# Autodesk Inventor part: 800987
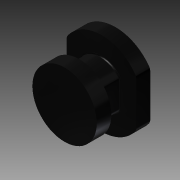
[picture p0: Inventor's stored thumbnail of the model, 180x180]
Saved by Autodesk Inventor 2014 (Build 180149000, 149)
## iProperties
Created: 2007-10
Part Number: 800987
Document SubType Name: Modeling
Designer: TH
Density: 7.85 g/cm^3
Mass: 11.8933 g
Surface Area: 10.7394 cm^2
Volume: 1.51507 cm^3
Material: Steel
Description: CONNECTOR PIN
Appearance: Glossy - Black
Component Category: Fasteners
Author: TH
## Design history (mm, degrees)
sketch "Sketch1"
  geometry: L1 (0, 0)-(0, -10.95); L2 (0, -10.95)-(6.925, -10.95); L3 (6.925, -10.95)-(6.925, -7.8); L4 (6.925, -7.8)-(5, -7.8); L5 (5, -7.8)-(5, -3); L6 (5, -3)-(9, -3); L7 (9, -3)-(9, 0); L8 (9, 0)-(0, 0)
  constraints: 16 end point, 6 parallel, 1 perpendicular, 1 vertical
  dimensions: "d0" = 6.925 distance of L1.end L2.end; "d1" = 5 distance between parallel lines of L1 L5; "d2" = 9 distance between parallel lines of L1 L7; "d3" = 3.15 distance of L2.end L3.end; "d4" = 4.8 distance of L4.end L5.end; "d5" = 3 distance of L6.end L7.end
revolve "Revolution1" sketch "Sketch1" stored, may be unused: angle "d6" = 90 deg
sketch "Sketch2"
  geometry: L1 (0, 12.6)-(0, -12.6) reference; L2 (7.5, 4.975)-(7.5, -4.975); L3 (-7.5, 4.975)-(-7.5, -4.975); A1 r 9 centre (0, 0) between (7.5, 4.975) and (7.5, -4.975) reference
  constraints: 4 end point, 4 point on circle, 2 parallel
  dimensions: "d7" = 15 distance between parallel lines of L3 L2; "d8" = 7.5 distance between parallel lines of L1 L3 (= 0.5 x d7)
extrude "Extrusion1" cut sketch "Sketch2" stored distance "d9" = 10; taper "d10" = 0 deg
sketch "Sketch3"
  geometry: L1 (7.5, -4.975)-(7.5, 4.975) reference; L2 (-4, -3)-(-4, 3); L3 (4, -3)-(4, 3); A1 r 9 centre (0, 0) between (-7.5, -4.975) and (7.5, -4.975) reference; A2 r 5 centre (0, 0) between (-4, -3) and (-4, 3) reference
  constraints: 4 end point, 4 point on circle, 2 parallel
  dimensions: "d11" = 8 distance between parallel lines of L3 L2; "d12" = 4 distance from line of A1.centre L3 (= 0.5 x d11)
extrude "Extrusion2" cut sketch "Sketch3" stored distance "d13" = 10; taper "d14" = 0 deg
fillet "Fillet1" dims "d15" = 1
fillet "Fillet2" dims "d16" = 1.5
fillet "Fillet3" dims "d17" = 0.3
body "Solid1"
